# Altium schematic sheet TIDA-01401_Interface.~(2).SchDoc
size 431 x 279 mm; Date: Not shown in title block; ApprovedBy: Not shown in title block; CheckedBy: Not shown in title block; Author: Not shown in title block; CompanyName: Not shown in title block; Engineer: Not shown in title block; Organization: Not shown in title block; Address1: Not shown in title block; Address2: Not shown in title block; Address3: Not shown in title block; Address4: Not shown in title block; DocumentNumber: 1; Revision: Use project parameter SCH_Rev; SheetNumber: 2; SheetTotal: 3; PageSetup: Record=PageOptions¦CenterHorizontal=True¦CenterVertical=True¦PrintScale=0.64¦XCorrection=1.00¦YCorrection=1.00¦PrintKind=0¦BorderSize=5000000¦LeftOffset=0¦BottomOffset=0¦Orientation=2¦PaperLength=1000¦PaperWidth=1000¦Scale=100¦PaperSource=15¦PrintQuality=600¦MediaType=1¦DitherType=10¦PrintScaleMode=1¦PaperKind=8 1/2x11¦PaperIndex=1
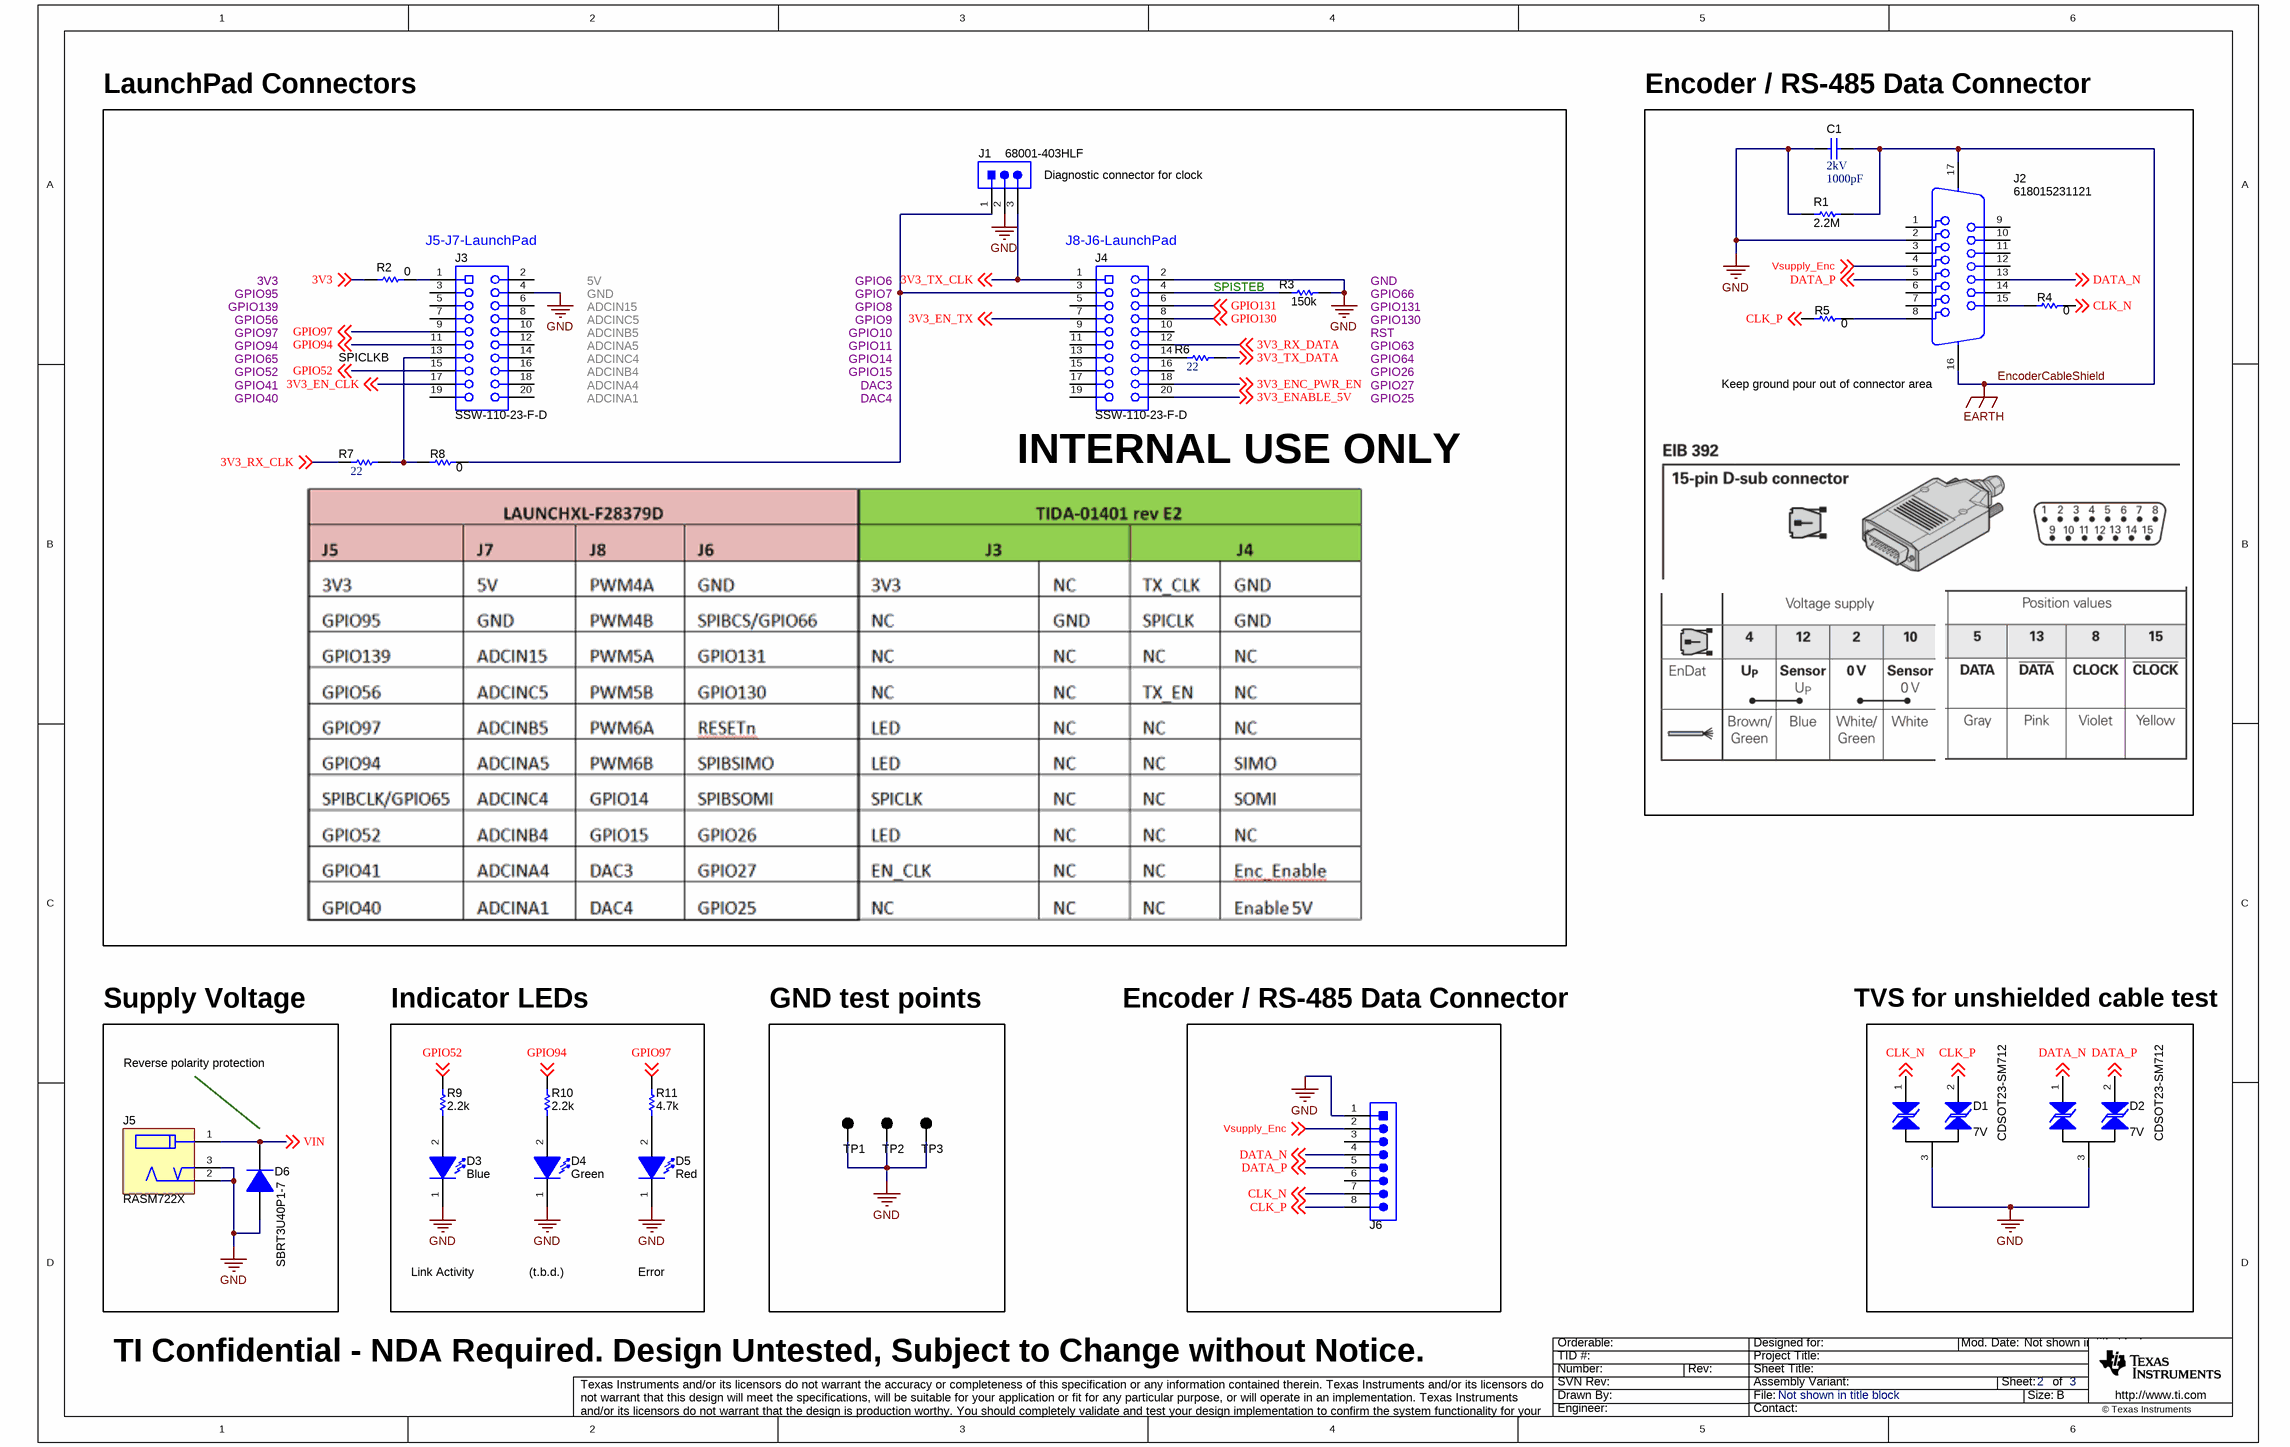
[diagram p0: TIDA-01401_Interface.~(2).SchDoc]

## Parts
C1  VDC_V: 2kV  ValueDisplayed: 1000pF  [1812_220]  (hidden comment: 1812GC102KAT1A)
D1  CDSOT23-SM712  value 7V  [SOT-23]
D2  CDSOT23-SM712  value 7V  [SOT-23]
D3  value Blue  [WL-SMCW_Blue]  (hidden comment: 150060BS75000)
D4  value Green  [WL-SMCW_GREEN]  (hidden comment: 150060GS75000)
D5  value Red  [WL-SMCW_RED]  (hidden comment: 150060RS75000)
D6  SBRT3U40P1-7  [PowerDI123]
J1  68001-403HLF  [FCI_68001-403HLF]
J2  618015231121  [Wurth_618015231121]
J3  SSW-110-23-F-D  [CONN_SSW-110-23-F-D]
J4  SSW-110-23-F-D  [CONN_SSW-110-23-F-D]
J5  RASM722X  [Switchcraft_RASM722]
J6  PEC08SAAN  [SULLINS_PEC08SAAN]  (value not drawn)
R1  ValueDisplayed: 2.2M  [1206]  (hidden comment: CRCW12062M20JNEA)
R2  ValueDisplayed: 0  [0603]  (hidden comment: CRCW06030000Z0EA)
R3  ValueDisplayed: 150k  [0402S]  (hidden comment: CRCW0402150KJNED)
R4  ValueDisplayed: 0  [0402S]  (hidden comment: CRCW04020000Z0ED)
R5  ValueDisplayed: 0  [0402S]  (hidden comment: CRCW04020000Z0ED)
R6  ValueDisplayed: 22  [0402S]  (hidden comment: CRCW040222R0JNED)
R7  ValueDisplayed: 22  [0402S]  (hidden comment: CRCW040222R0JNED)
R8  ValueDisplayed: 0  [0402S]  (hidden comment: CRCW04020000Z0ED)
R9  ValueDisplayed: 2.2k  [0402S]  (hidden comment: CRCW04022K20JNED)
R10  ValueDisplayed: 2.2k  [0402S]  (hidden comment: CRCW04022K20JNED)
R11  ValueDisplayed: 4.7k  [0402S]  (hidden comment: CRCW04024K70JNED)
TP1  5001  [Keystone5001]  (value not drawn)
TP2  5001  [Keystone5001]  (value not drawn)
TP3  5001  [Keystone5001]  (value not drawn)

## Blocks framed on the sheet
INTERNAL USE ONLY: J1 J3 J4 R2 R3 R6-R8
Keep ground pour out of connector area: C1 J2 R1 R4 R5
Reverse polarity protection: D6 J5

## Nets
EncoderCableShield: C1.1 J2.16(MH1) J2.17(MH2) R1.2  [also labelled EARTH]
GND: C1.2 D1.3 D2.3 D3.1(K) D4.1(K) D5.1(K) D6.2(A) J1.2 J2.2 J3.4 J4.2 J5.2 J5.3 J6.1 R1.1 R3.2 TP1.1 TP2.1 TP3.1
3V3: R2.1 ; off-sheet 3V3
3V3_EN_CLK: J3.17 ; off-sheet 3V3_EN_CLK
3V3_EN_TX: J4.7 ; off-sheet 3V3_EN_TX
3V3_ENABLE_5V: J4.20 ; off-sheet 3V3_ENABLE_5V
3V3_ENC_PWR_EN: J4.18 ; off-sheet 3V3_ENC_PWR_EN
3V3_RX_CLK: R7.1 ; off-sheet 3V3_RX_CLK
3V3_RX_DATA: J4.12 ; off-sheet 3V3_RX_DATA
3V3_TX_CLK: J1.3 J4.1 ; off-sheet 3V3_TX_CLK
3V3_TX_DATA: R6.2 ; off-sheet 3V3_TX_DATA
CLK_N: D1.1 J6.7 R4.2 ; off-sheet CLK_N
CLK_P: D1.2 J6.8 R5.1 ; off-sheet CLK_P
DATA_N: D2.1 J2.13 J6.4 ; off-sheet DATA_N
DATA_P: D2.2 J2.5 J6.5 ; off-sheet DATA_P
GPIO52: J3.15 R9.2 ; off-sheet GPIO52
GPIO94: J3.11 R10.2 ; off-sheet GPIO94
GPIO97: J3.9 R11.2 ; off-sheet GPIO97
GPIO130: J4.8 ; off-sheet GPIO130
GPIO131: J4.6 ; off-sheet GPIO131
VIN: D6.1(K) J5.1 ; off-sheet VIN
Vsupply_Enc: J2.4 J6.2 ; off-sheet Vsupply_Enc
NetD3_2: D3.2(A) R9.1
NetD4_2: D4.2(A) R10.1
NetD5_2: D5.2(A) R11.1
NetJ1_1: J1.1 J4.3 R8.2
NetJ2_8: J2.8 R5.2
NetJ2_15: J2.15 R4.1
NetJ3_1: J3.1 R2.2
NetJ3_13: J3.13 R7.2 R8.1
NetJ4_4: J4.4 R3.1
NetJ4_14: J4.14 R6.1

Not connected (* = marked no-connect by the designer): J2 1 3 6 7 9 10 11 12 14; J3 2 3 5 6 7 8 10 12 14 16 18 19 20; J4 5 9 10 11 13 15 16 17 19; J6 3 6

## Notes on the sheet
- LaunchPad Connectors
- (near C1) Encoder / RS-485 Data Connector
- (near J1) Diagnostic connector for clock
- J5-J7-LaunchPad
- (near J4) J8-J6-LaunchPad
- (near R3) SPISTEB
- SPICLKB
- 3V3
  GPIO95
  GPIO139
  GPIO56
  GPIO97
  GPIO94
  GPIO65
  GPIO52
  GPIO41
  GPIO40
- 5V
  GND
  ADCIN15
  ADCINC5
  ADCINB5
  ADCINA5
  ADCINC4
  ADCINB4
  ADCINA4
  ADCINA1
- GPIO6
  GPIO7
  GPIO8
  GPIO9
  GPIO10
  GPIO11
  GPIO14
  GPIO15
  DAC3
  DAC4
- GND
  GPIO66
  GPIO131
  GPIO130
  RST
  GPIO63
  GPIO64
  GPIO26
  GPIO27
  GPIO25
- Supply Voltage
- Indicator LEDs
- GND test points
- Encoder / RS-485 Data Connector
- TVS for unshielded cable test
- Link Activity
- (t.b.d.)
- Error
- TI Confidential - NDA Required. Design Untested, Subject to Change without Notice.

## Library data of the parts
C1 = CMP-0064918-2: CAP, CERM, 1000 pF, 2000 V,+/- 10%, X7R, 1812; Manufacturer: AVX; TaMin_C: -55°C; Polarized: N; SizeAreaWB_mm2: 23.1; Value1: Unknown; U/M: EA; Value: 1000pF; TaMax_C: 125°C; SizeZ_mm: 2.2; SizeX_mm: 4.5; SizeY_mm: 3.2; Cap_Case: 1812; Value2: 2000V; SizeArea_mm2: 14.4; CompType: Capacitor; Cap_F: 1nF; AEC Category: Q200
D1 D2 = CDSOT23-SM712: Diode, TVS, Bi, 7 V, SOT-23; Manufacturer: Bourns; SymbolCreator: a0411947; U/M: EA; Vr_V: 7; Value1: W; SizeAreaWB_mm2: 14; SizeArea_mm2: 7.5; SizeX_mm: 2.5; SizeY_mm: 3; SizeZ_mm: 1.1; AEC Category: Q101
D3 = 150060BS75000: LED, Blue, SMD; Manufacturer: Wurth Elektronik; Type: InGaN; Vf_V: 3.2; Value2: 3.2V; Io_A: 0.03; Vr_V: 5; Tjmax_C: 85; Power_TotalModule: 0.105; Value1: 0.105W; Angle: 140; U/M: EA
D4 = 150060GS75000: LED, Green, SMD; Manufacturer: Wurth Elektronik; Type: InGaN; Vf_V: 3.2; Value2: 3.2V; Io_A: 0.02; Tjmax_C: 85; Value1: W; Angle: 140; U/M: EA
D5 = 150060RS75000: LED, Red, SMD; Manufacturer: Wurth Elektronik; Type: AlInGaP; Vf_V: 2; Value2: 2V; Io_A: 0.03; Vr_V: 5; Tjmax_C: 85; Power_TotalModule: 0.072; Value1: 0.072W; Angle: 140; U/M: EA
D6 = SBRT3U40P1-7: Diode, Super Barrier Rectifier, 40 V, 3 A, AEC-Q101, PowerDI123; Manufacturer: Diodes Inc.; U/M: EA; Vf_V: 0.49; Value: 40V; Value1: 3A; Value2: 0.49V; Io_A: 3; Vr_V: 40; TJmax_C: 150; RJC_CperW: 19; SizeAreaWB_mm2: 13.066; SizeArea_mm2: 6.586; SizeX_mm: 3.7; SizeY_mm: 1.78; SizeZ_mm: 0.98; AEC Category: Q101; AEC Qualified: Y
J1 = 68001-403HLF: Header, 2.54mm, 3x1, Tin, TH; Manufacturer: FCI; SymbolCreator: a0799628; Pitch_mm: 2.54; Gender: Male; Shrouded: N; Row_Count: 1; Current_A: 3; Voltage_V: 1500; Cert_CSA: Y
J2 = CMP-0077259-1: Receptacle, D-Sub, 15 Position, R/A, TH; Manufacturer: Wurth Elektronik; Pitch_mm: 2.77; Gender: Female; Cert_UL: Y; Current_A: 3A; Voltage_V: 125V; ContactFinish: Gold; RowSpacing_mm: 2.84; Row_Count: 2
J3 J4 = SSW-110-23-F-D: Connector, Receptacle, 100mil, 10x2, Gold plated, TH; Manufacturer: Samtec; SymbolCreator: a0412235
J5 = RASM722X: Power Jack, 2mm, R/A, SMD; Manufacturer: Switchcraft; SymbolCreator: a0799628
J6 = PEC08SAAN: Header, 100mil, 8x1, Tin, TH; Manufacturer: Sullins Connector Solutions; SymbolCreator: a0411947; Pitch_mm: 2.54; Gender: Male; Shrouded: N; Row_Count: 1; Current_A: 3; Voltage_V: 1800; Cert_UL: Y
R1 = CRCW12062M20JNEA: RES, 2.2 M, 5%, 0.25 W, 1206; Manufacturer: Vishay-Dale; CompType: Resistor; Value: 2.2Meg; Res_ohm: 2200000; Value_Code: 2M20; Tolerance_%: 5; Power_W: 0.25; Value2: 0.25W; VDC_V: 200; TempCo: 200 ppm/C; SizeArea_mm2: 5.12; SizeX_mm: 3.2; SizeY_mm: 1.6; SizeZ_mm: 1.35; EIA_Code: E24; U/M: EA; AEC Category: Q200
R2 = CRCW06030000Z0EA: RES, 0, 5%, 0.1 W, 0603; Manufacturer: Vishay-Dale; CompType: Resistor; Value: 0; Value_Code: 0000; Tolerance_%: 5; Power_W: 0.1; Value2: 0.1W; VDC_V: 75; TempCo: 200 ppm/C; SizeArea_mm2: 1.28; SizeX_mm: 1.6; SizeY_mm: 0.8; SizeZ_mm: 1; EIA_Code: E24; U/M: EA; AEC Category: Q200
R3 = CRCW0402150KJNED: RES, 150 k, 5%, 0.063 W, 0402; Manufacturer: Vishay-Dale; CompType: Resistor; Value: 150k; Res_ohm: 150000; Tolerance_%: 5; Power_W: 0.063; Value2: 0.063W; VDC_V: 50; TempCo: 200 ppm/C; SizeArea_mm2: 0.5; SizeX_mm: 1; SizeZ_mm: 0.6; EIA_Code: E24; U/M: EA; AEC Category: Q200
R4 R5 R8 = CRCW04020000Z0ED: RES, 0, 5%, 0.063 W, 0402; Manufacturer: Vishay-Dale; CompType: Resistor; Value: 0; Value_Code: 0000; Tolerance_%: 5; Power_W: 0.063; Value2: 0.063W; VDC_V: 50; TempCo: 200 ppm/C; SizeArea_mm2: 0.5; SizeX_mm: 1; SizeZ_mm: 0.6; EIA_Code: E24; U/M: EA; AEC Category: Q200
R6 R7 = CMP-0026880-2: RES, 22, 5%, 0.063 W, 0402; Manufacturer: Vishay-Dale; Power_W: 63mW; TempCo: 200 ppm/C; Value_Code: 22R0; U/M: EA; Value: 22; EIA_Code: E24; SizeX_mm: 1; SizeY_mm: 0.5; SizeZ_mm: 0.6; Value2: 0.063W; CompType: Resistor; VDC_V: 50V; AEC Category: Q200
R9 R10 = CRCW04022K20JNED: RES, 2.2 k, 5%, 0.063 W, 0402; Manufacturer: Vishay-Dale; CompType: Resistor; Value: 2.2k; Res_ohm: 2200; Value_Code: 2k20; Tolerance_%: 5; Power_W: 0.063; Value2: 0.063W; VDC_V: 50; TempCo: 200 ppm/C; SizeArea_mm2: 0.5; SizeX_mm: 1; SizeZ_mm: 0.6; EIA_Code: E24; U/M: EA; AEC Category: Q200
R11 = CRCW04024K70JNED: RES, 4.7 k, 5%, 0.063 W, 0402; Manufacturer: Vishay-Dale; CompType: Resistor; Value: 4.7k; Res_ohm: 4700; Value_Code: 4k70; Tolerance_%: 5; Power_W: 0.063; Value2: 0.063W; VDC_V: 50; TempCo: 200 ppm/C; SizeArea_mm2: 0.5; SizeX_mm: 1; SizeZ_mm: 0.6; EIA_Code: E24; U/M: EA; AEC Category: Q200
TP1-TP3 = 5001: Test Point, Miniature, Black, TH; Manufacturer: Keystone; CompType: Test Point Loop; ContactFinish: Silver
